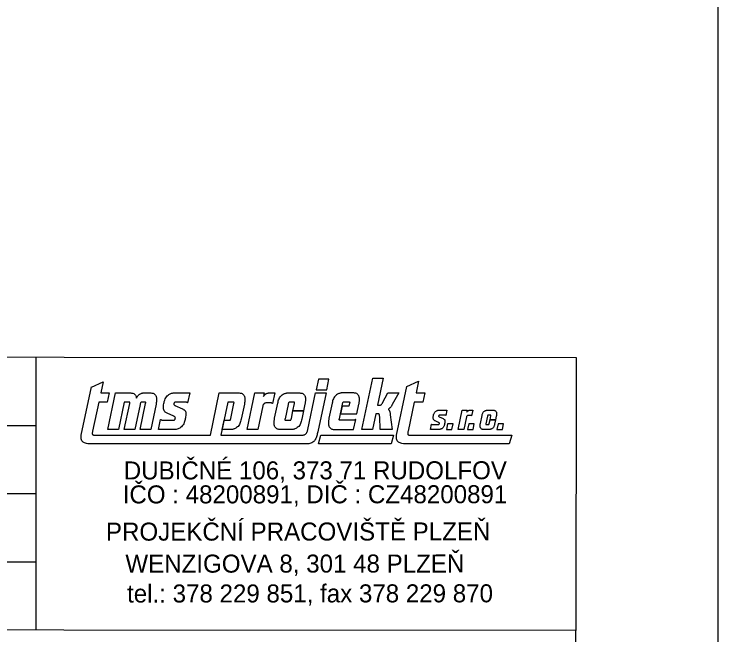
# Model space of a CAD drawing. Extents: x -467927 to -455912, y -1105662 to -1104439.
# Drawn here: x -458564.6 to -458490.4, y -1104682 to -1104616.5 of the extents above; entities that cross this region are included whole.
import ezdxf

# ---------------------------------------------------------------- set-up
doc = ezdxf.new("R2010")
doc.units = 0
doc.layers.add('Implicitní', color=7, linetype='Continuous')
doc.layers.add('Vše', color=7, linetype='Continuous')

msp = doc.modelspace()

# ---------------------------------------------------------------- linework, layer by layer
at = {"layer": 'Implicitní'}
for p, q in [((-458562.268, -1104652.701), (-458562.289, -1104681.501)), ((-458556.421, -1104655.845), (-458555.189, -1104655.283)), ((-458555.189, -1104655.283), (-458555.438, -1104656.467)), ((-458532.478, -1104655.021), (-458532.714, -1104656.139)), ((-458531.365, -1104655.021), (-458532.478, -1104655.021)), ((-458531.601, -1104656.139), (-458531.365, -1104655.021)), ((-458527.893, -1104660.331), (-458526.751, -1104654.911)), ((-458526.751, -1104654.911), (-458525.638, -1104654.911)), ((-458525.638, -1104654.911), (-458526.236, -1104657.75)), ((-458523.15, -1104655.796), (-458521.919, -1104655.235)), ((-458521.919, -1104655.235), (-458522.179, -1104656.467)), ((-458557.49, -1104660.925), (-458556.421, -1104655.844)), ((-458524.23, -1104660.925), (-458523.15, -1104655.796)), ((-458555.438, -1104656.467), (-458554.536, -1104656.467)), ((-458554.536, -1104656.467), (-458554.74, -1104657.433)), ((-458554.689, -1104660.331), (-458553.875, -1104656.467)), ((-458553.875, -1104656.467), (-458552.445, -1104656.467)), ((-458550.942, -1104656.467), (-458550.328, -1104656.467)), ((-458547.67, -1104656.467), (-458546.051, -1104656.467)), ((-458546.051, -1104656.467), (-458546.273, -1104657.52)), ((-458543.866, -1104660.92), (-458542.929, -1104656.467)), ((-458542.929, -1104656.467), (-458541.015, -1104656.467)), ((-458539.982, -1104660.331), (-458539.168, -1104656.467)), ((-458539.168, -1104656.467), (-458538.197, -1104656.467)), ((-458538.197, -1104656.467), (-458538.273, -1104656.83)), ((-458537.68, -1104656.467), (-458537.079, -1104656.467)), ((-458537.079, -1104656.467), (-458537.315, -1104657.588)), ((-458535.634, -1104656.467), (-458534.623, -1104656.467)), ((-458533.595, -1104660.322), (-458532.783, -1104656.467)), ((-458532.783, -1104656.467), (-458531.67, -1104656.467)), ((-458532.714, -1104656.139), (-458531.601, -1104656.139)), ((-458531.67, -1104656.467), (-458532.538, -1104660.591)), ((-458528.93, -1104656.467), (-458529.904, -1104656.467)), ((-458525.718, -1104657.51), (-458525.175, -1104656.467)), ((-458525.175, -1104656.467), (-458523.995, -1104656.467)), ((-458523.995, -1104656.467), (-458524.697, -1104657.697)), ((-458522.179, -1104656.467), (-458521.276, -1104656.467)), ((-458521.276, -1104656.467), (-458521.48, -1104657.433)), ((-458555.642, -1104657.433), (-458556.291, -1104660.517)), ((-458554.74, -1104657.433), (-458555.642, -1104657.433)), ((-458552.965, -1104657.433), (-458553.576, -1104660.331)), ((-458552.47, -1104657.433), (-458552.965, -1104657.433)), ((-458552.959, -1104660.331), (-458552.379, -1104657.576)), ((-458551.28, -1104660.331), (-458550.701, -1104657.577)), ((-458550.792, -1104657.433), (-458551.089, -1104657.433)), ((-458546.56, -1104657.433), (-458547.511, -1104657.433)), ((-458542.019, -1104657.433), (-458542.753, -1104660.92)), ((-458541.48, -1104657.433), (-458542.019, -1104657.433)), ((-458541.724, -1104659.163), (-458541.389, -1104657.575)), ((-458537.602, -1104657.5), (-458537.896, -1104657.5)), ((-458537.1, -1104659.144), (-458536.764, -1104657.548)), ((-458535.087, -1104657.433), (-458535.481, -1104657.433)), ((-458535.164, -1104658.369), (-458534.997, -1104657.575)), ((-458531.033, -1104657.55), (-458531.369, -1104659.142)), ((-458529.74, -1104657.396), (-458529.284, -1104657.396)), ((-458529.193, -1104657.539), (-458529.262, -1104657.865)), ((-458522.382, -1104657.433), (-458523.031, -1104660.517)), ((-458521.48, -1104657.433), (-458522.382, -1104657.433)), ((-458551.289, -1104657.687), (-458551.846, -1104660.331)), ((-458549.602, -1104657.647), (-458550.167, -1104660.331)), ((-458547.613, -1104657.789), (-458546.824, -1104658.141)), ((-458540.292, -1104657.649), (-458540.628, -1104659.246)), ((-458538.34, -1104657.822), (-458538.868, -1104660.331)), ((-458535.68, -1104657.687), (-458536.001, -1104659.214)), ((-458533.895, -1104657.652), (-458534.046, -1104658.369)), ((-458530.27, -1104659.214), (-458529.942, -1104657.654)), ((-458529.986, -1104657.865), (-458530.16, -1104658.688)), ((-458529.262, -1104657.865), (-458529.986, -1104657.865)), ((-458528.422, -1104658.688), (-458528.204, -1104657.653)), ((-458526.236, -1104657.75), (-458525.994, -1104657.75)), ((-458519.773, -1104658.295), (-458518.923, -1104658.295)), ((-458518.923, -1104658.295), (-458519.04, -1104658.848)), ((-458517.732, -1104660.323), (-458517.305, -1104658.295)), ((-458517.305, -1104658.295), (-458516.795, -1104658.295)), ((-458516.795, -1104658.295), (-458516.835, -1104658.485)), ((-458516.524, -1104658.295), (-458516.208, -1104658.295)), ((-458516.208, -1104658.295), (-458516.332, -1104658.883)), ((-458514.633, -1104658.295), (-458514.102, -1104658.295)), ((-458547.73, -1104658.933), (-458548.422, -1104658.623)), ((-458535.331, -1104659.163), (-458535.164, -1104658.369)), ((-458535.164, -1104658.369), (-458534.046, -1104658.369)), ((-458534.046, -1104658.369), (-458535.164, -1104658.369)), ((-458534.046, -1104658.369), (-458534.231, -1104659.248)), ((-458530.16, -1104658.688), (-458528.422, -1104658.688)), ((-458526.432, -1104658.68), (-458526.78, -1104660.331)), ((-458526.237, -1104658.68), (-458526.432, -1104658.68)), ((-458525.973, -1104660.331), (-458526.021, -1104659.005)), ((-458524.897, -1104658.782), (-458524.713, -1104660.331)), ((-458519.743, -1104658.988), (-458519.329, -1104659.173)), ((-458519.191, -1104658.802), (-458519.69, -1104658.802)), ((-458516.87, -1104659.006), (-458517.147, -1104660.323)), ((-458516.483, -1104658.837), (-458516.637, -1104658.837)), ((-458515.403, -1104659.7), (-458515.226, -1104658.862)), ((-458514.657, -1104658.935), (-458514.826, -1104659.737)), ((-458514.346, -1104658.802), (-458514.553, -1104658.802)), ((-458514.386, -1104659.293), (-458514.299, -1104658.876)), ((-458513.72, -1104658.917), (-458513.8, -1104659.293)), ((-458667.313, -1104659.823), (-458562.274, -1104659.9)), ((-458549.354, -1104660.331), (-458549.13, -1104659.269)), ((-458548.841, -1104659.357), (-458547.781, -1104659.357)), ((-458542.629, -1104660.331), (-458542.424, -1104659.357)), ((-458542.424, -1104659.357), (-458541.895, -1104659.357)), ((-458535.91, -1104659.357), (-458535.503, -1104659.357)), ((-458528.881, -1104659.357), (-458530.179, -1104659.357)), ((-458528.768, -1104660.331), (-458528.544, -1104659.267)), ((-458520.657, -1104660.323), (-458520.54, -1104659.766)), ((-458520.388, -1104659.812), (-458519.831, -1104659.812)), ((-458519.805, -1104659.589), (-458520.168, -1104659.427)), ((-458518.861, -1104659.736), (-458518.985, -1104660.323)), ((-458518.277, -1104659.736), (-458518.861, -1104659.736)), ((-458518.4, -1104660.323), (-458518.277, -1104659.736)), ((-458516.625, -1104659.736), (-458516.749, -1104660.323)), ((-458516.041, -1104659.736), (-458516.625, -1104659.736)), ((-458516.165, -1104660.323), (-458516.041, -1104659.736)), ((-458514.778, -1104659.812), (-458514.564, -1104659.812)), ((-458514.474, -1104659.71), (-458514.386, -1104659.293)), ((-458514.386, -1104659.293), (-458513.8, -1104659.293)), ((-458513.8, -1104659.293), (-458514.386, -1104659.293)), ((-458513.8, -1104659.293), (-458513.897, -1104659.755)), ((-458513.536, -1104659.736), (-458513.66, -1104660.323)), ((-458512.952, -1104659.736), (-458513.536, -1104659.736)), ((-458513.075, -1104660.323), (-458512.952, -1104659.736)), ((-458553.576, -1104660.331), (-458554.689, -1104660.331)), ((-458551.846, -1104660.331), (-458552.959, -1104660.331)), ((-458550.167, -1104660.331), (-458551.28, -1104660.331)), ((-458547.718, -1104660.331), (-458549.354, -1104660.331)), ((-458541.759, -1104660.331), (-458542.629, -1104660.331)), ((-458538.868, -1104660.331), (-458539.982, -1104660.331)), ((-458535.362, -1104660.331), (-458536.375, -1104660.331)), ((-458530.645, -1104660.331), (-458528.768, -1104660.331)), ((-458526.78, -1104660.331), (-458527.893, -1104660.331)), ((-458524.713, -1104660.331), (-458525.973, -1104660.331)), ((-458519.798, -1104660.323), (-458520.657, -1104660.323)), ((-458518.985, -1104660.323), (-458518.4, -1104660.323)), ((-458517.147, -1104660.323), (-458517.732, -1104660.323)), ((-458516.749, -1104660.323), (-458516.165, -1104660.323)), ((-458514.49, -1104660.323), (-458515.022, -1104660.323)), ((-458513.66, -1104660.323), (-458513.075, -1104660.323)), ((-458556.106, -1104660.92), (-458543.866, -1104660.92)), ((-458542.753, -1104660.92), (-458534.206, -1104660.92)), ((-458532.485, -1104661.848), (-458532.229, -1104660.92)), ((-458532.229, -1104660.92), (-458524.567, -1104660.92)), ((-458524.567, -1104660.92), (-458524.823, -1104661.848)), ((-458522.846, -1104660.92), (-458512.092, -1104660.92)), ((-458512.092, -1104660.92), (-458512.349, -1104661.848)), ((-458533.653, -1104661.848), (-458556.616, -1104661.848)), ((-458524.823, -1104661.848), (-458532.485, -1104661.848)), ((-458512.349, -1104661.848), (-458523.356, -1104661.848)), ((-458667.318, -1104667.023), (-458562.279, -1104667.1)), ((-458667.323, -1104674.223), (-458562.284, -1104674.3))]:
    msp.add_line(p, q, dxfattribs=at)
for points in [[(-458667.307, -1104652.623), (-458505.302, -1104652.742), (-458505.323, -1104681.543), (-458667.328, -1104681.424)], [(-458667.332, -1104688.623), (-458505.329, -1104688.742), (-458505.323, -1104681.543), (-458667.326, -1104681.424)]]:
    msp.add_lwpolyline(points, close=True, dxfattribs=at)
for points in [[(-458552.445, -1104656.467), (-458552.353, -1104656.468), (-458552.176, -1104656.481), (-458552.033, -1104656.512), (-458551.889, -1104656.596), (-458551.715, -1104656.826), (-458551.685, -1104656.938), (-458551.673, -1104656.986), (-458551.666, -1104657.015)], [(-458551.666, -1104657.015), (-458551.562, -1104656.84), (-458551.454, -1104656.712), (-458551.319, -1104656.601), (-458551.227, -1104656.549), (-458551.121, -1104656.505), (-458551.037, -1104656.484), (-458550.942, -1104656.467)], [(-458550.328, -1104656.467), (-458550.236, -1104656.468), (-458550.06, -1104656.481), (-458549.916, -1104656.512), (-458549.773, -1104656.596), (-458549.599, -1104656.826), (-458549.569, -1104656.938), (-458549.556, -1104656.986), (-458549.561, -1104657.341), (-458549.579, -1104657.501), (-458549.602, -1104657.647)], [(-458548.422, -1104658.623), (-458548.566, -1104658.53), (-458548.677, -1104658.435), (-458548.778, -1104658.261), (-458548.816, -1104658.057), (-458548.82, -1104657.859), (-458548.784, -1104657.574), (-458548.733, -1104657.362), (-458548.634, -1104657.103), (-458548.505, -1104656.881), (-458548.341, -1104656.715), (-458548.123, -1104656.564), (-458547.955, -1104656.499), (-458547.792, -1104656.469), (-458547.67, -1104656.467)], [(-458541.015, -1104656.467), (-458540.923, -1104656.468), (-458540.747, -1104656.481), (-458540.603, -1104656.512), (-458540.46, -1104656.596), (-458540.285, -1104656.826), (-458540.255, -1104656.938), (-458540.243, -1104656.986), (-458540.247, -1104657.341), (-458540.265, -1104657.501), (-458540.292, -1104657.649)], [(-458538.273, -1104656.83), (-458538.203, -1104656.732), (-458538.147, -1104656.669), (-458538.061, -1104656.594), (-458537.985, -1104656.548), (-458537.88, -1104656.501), (-458537.79, -1104656.478), (-458537.68, -1104656.467)], [(-458536.764, -1104657.548), (-458536.713, -1104657.322), (-458536.632, -1104657.092), (-458536.505, -1104656.874), (-458536.379, -1104656.732), (-458536.199, -1104656.613), (-458536.046, -1104656.539), (-458535.916, -1104656.496), (-458535.795, -1104656.471), (-458535.634, -1104656.467)], [(-458534.623, -1104656.467), (-458534.531, -1104656.468), (-458534.355, -1104656.481), (-458534.211, -1104656.512), (-458534.068, -1104656.596), (-458533.893, -1104656.826), (-458533.863, -1104656.938), (-458533.851, -1104656.986), (-458533.855, -1104657.341), (-458533.873, -1104657.501), (-458533.895, -1104657.652)], [(-458529.904, -1104656.467), (-458530.064, -1104656.471), (-458530.185, -1104656.496), (-458530.316, -1104656.539), (-458530.468, -1104656.613), (-458530.648, -1104656.732), (-458530.775, -1104656.874), (-458530.902, -1104657.092), (-458530.983, -1104657.322), (-458531.033, -1104657.55)], [(-458528.204, -1104657.653), (-458528.181, -1104657.501), (-458528.163, -1104657.341), (-458528.158, -1104656.986), (-458528.171, -1104656.938), (-458528.201, -1104656.826), (-458528.375, -1104656.596), (-458528.519, -1104656.512), (-458528.662, -1104656.481), (-458528.838, -1104656.468), (-458528.93, -1104656.467)], [(-458552.379, -1104657.576), (-458552.373, -1104657.542), (-458552.368, -1104657.503), (-458552.374, -1104657.469), (-458552.392, -1104657.445), (-458552.426, -1104657.435), (-458552.47, -1104657.433)], [(-458551.089, -1104657.433), (-458551.117, -1104657.434), (-458551.15, -1104657.442), (-458551.184, -1104657.463), (-458551.228, -1104657.51), (-458551.25, -1104657.556), (-458551.289, -1104657.687)], [(-458550.701, -1104657.577), (-458550.695, -1104657.542), (-458550.69, -1104657.503), (-458550.696, -1104657.469), (-458550.714, -1104657.445), (-458550.747, -1104657.435), (-458550.792, -1104657.433)], [(-458547.511, -1104657.433), (-458547.587, -1104657.44), (-458547.629, -1104657.461), (-458547.673, -1104657.497), (-458547.704, -1104657.55), (-458547.723, -1104657.613), (-458547.725, -1104657.681), (-458547.705, -1104657.726), (-458547.661, -1104657.759), (-458547.613, -1104657.789)], [(-458546.273, -1104657.52), (-458546.336, -1104657.485), (-458546.401, -1104657.457), (-458546.441, -1104657.445), (-458546.51, -1104657.435), (-458546.56, -1104657.433)], [(-458541.389, -1104657.575), (-458541.383, -1104657.542), (-458541.378, -1104657.503), (-458541.384, -1104657.469), (-458541.402, -1104657.445), (-458541.435, -1104657.435), (-458541.48, -1104657.433)], [(-458537.896, -1104657.5), (-458537.967, -1104657.506), (-458538.037, -1104657.519), (-458538.12, -1104657.553), (-458538.191, -1104657.593), (-458538.246, -1104657.642), (-458538.308, -1104657.727), (-458538.34, -1104657.822)], [(-458537.315, -1104657.588), (-458537.379, -1104657.552), (-458537.444, -1104657.524), (-458537.483, -1104657.512), (-458537.535, -1104657.504), (-458537.602, -1104657.5)], [(-458535.481, -1104657.433), (-458535.509, -1104657.434), (-458535.542, -1104657.442), (-458535.576, -1104657.463), (-458535.62, -1104657.51), (-458535.642, -1104657.556), (-458535.681, -1104657.687)], [(-458534.997, -1104657.575), (-458534.99, -1104657.542), (-458534.985, -1104657.503), (-458534.991, -1104657.469), (-458535.01, -1104657.445), (-458535.043, -1104657.435), (-458535.087, -1104657.433)], [(-458529.942, -1104657.654), (-458529.902, -1104657.52), (-458529.879, -1104657.473), (-458529.836, -1104657.427), (-458529.802, -1104657.406), (-458529.769, -1104657.398), (-458529.74, -1104657.396)], [(-458529.284, -1104657.396), (-458529.239, -1104657.398), (-458529.206, -1104657.408), (-458529.188, -1104657.432), (-458529.181, -1104657.467), (-458529.186, -1104657.505), (-458529.193, -1104657.539)], [(-458525.994, -1104657.75), (-458525.925, -1104657.747), (-458525.898, -1104657.738), (-458525.858, -1104657.713), (-458525.826, -1104657.677), (-458525.734, -1104657.54), (-458525.718, -1104657.51)], [(-458546.824, -1104658.141), (-458546.771, -1104658.167), (-458546.666, -1104658.237), (-458546.587, -1104658.306), (-458546.511, -1104658.405), (-458546.477, -1104658.492), (-458546.454, -1104658.728), (-458546.486, -1104658.993), (-458546.571, -1104659.387), (-458546.636, -1104659.595), (-458546.753, -1104659.836), (-458546.931, -1104660.048), (-458547.102, -1104660.179), (-458547.286, -1104660.27), (-458547.49, -1104660.319), (-458547.718, -1104660.331)], [(-458524.697, -1104657.697), (-458524.788, -1104657.856), (-458524.859, -1104657.956), (-458524.934, -1104658.035), (-458524.999, -1104658.094), (-458525.103, -1104658.172)], [(-458525.103, -1104658.172), (-458525.053, -1104658.254), (-458525.006, -1104658.329), (-458524.973, -1104658.395), (-458524.941, -1104658.498), (-458524.914, -1104658.638), (-458524.897, -1104658.782)], [(-458520.168, -1104659.427), (-458520.244, -1104659.378), (-458520.302, -1104659.328), (-458520.355, -1104659.236), (-458520.375, -1104659.129), (-458520.377, -1104659.025), (-458520.358, -1104658.876), (-458520.331, -1104658.764), (-458520.279, -1104658.628), (-458520.212, -1104658.512), (-458520.125, -1104658.425), (-458520.011, -1104658.346), (-458519.923, -1104658.311), (-458519.837, -1104658.296), (-458519.773, -1104658.295)], [(-458516.835, -1104658.485), (-458516.798, -1104658.434), (-458516.768, -1104658.401), (-458516.723, -1104658.361), (-458516.684, -1104658.337), (-458516.628, -1104658.313), (-458516.581, -1104658.301), (-458516.524, -1104658.295)], [(-458515.226, -1104658.862), (-458515.2, -1104658.743), (-458515.157, -1104658.623), (-458515.091, -1104658.508), (-458515.024, -1104658.434), (-458514.93, -1104658.371), (-458514.849, -1104658.332), (-458514.781, -1104658.31), (-458514.718, -1104658.297), (-458514.633, -1104658.295)], [(-458514.102, -1104658.294), (-458514.054, -1104658.295), (-458513.961, -1104658.302), (-458513.886, -1104658.318), (-458513.811, -1104658.362), (-458513.719, -1104658.483), (-458513.704, -1104658.542), (-458513.697, -1104658.567), (-458513.699, -1104658.754), (-458513.709, -1104658.837), (-458513.72, -1104658.917)], [(-458547.781, -1104659.357), (-458547.707, -1104659.353), (-458547.663, -1104659.327), (-458547.609, -1104659.268), (-458547.579, -1104659.195), (-458547.567, -1104659.102), (-458547.579, -1104659.044), (-458547.608, -1104659.006), (-458547.673, -1104658.966), (-458547.73, -1104658.933)], [(-458526.021, -1104659.005), (-458526.033, -1104658.856), (-458526.046, -1104658.754), (-458526.078, -1104658.717), (-458526.122, -1104658.693), (-458526.16, -1104658.683), (-458526.237, -1104658.68)], [(-458519.69, -1104658.802), (-458519.73, -1104658.805), (-458519.751, -1104658.816), (-458519.775, -1104658.835), (-458519.791, -1104658.863), (-458519.801, -1104658.896), (-458519.802, -1104658.932), (-458519.791, -1104658.956), (-458519.769, -1104658.973), (-458519.743, -1104658.988)], [(-458519.04, -1104658.848), (-458519.073, -1104658.829), (-458519.107, -1104658.814), (-458519.128, -1104658.808), (-458519.164, -1104658.803), (-458519.191, -1104658.802)], [(-458516.637, -1104658.837), (-458516.674, -1104658.84), (-458516.711, -1104658.847), (-458516.754, -1104658.865), (-458516.792, -1104658.885), (-458516.821, -1104658.911), (-458516.853, -1104658.956), (-458516.87, -1104659.006)], [(-458516.332, -1104658.883), (-458516.365, -1104658.864), (-458516.4, -1104658.849), (-458516.42, -1104658.843), (-458516.447, -1104658.839), (-458516.483, -1104658.837)], [(-458514.553, -1104658.802), (-458514.567, -1104658.803), (-458514.585, -1104658.807), (-458514.603, -1104658.818), (-458514.626, -1104658.842), (-458514.638, -1104658.866), (-458514.658, -1104658.935)], [(-458514.299, -1104658.876), (-458514.295, -1104658.859), (-458514.292, -1104658.839), (-458514.296, -1104658.82), (-458514.305, -1104658.808), (-458514.323, -1104658.803), (-458514.346, -1104658.802)], [(-458549.13, -1104659.269), (-458549.067, -1104659.305), (-458549.002, -1104659.333), (-458548.963, -1104659.345), (-458548.893, -1104659.355), (-458548.841, -1104659.357)], [(-458541.895, -1104659.357), (-458541.828, -1104659.354), (-458541.783, -1104659.328), (-458541.756, -1104659.274), (-458541.741, -1104659.226), (-458541.724, -1104659.163)], [(-458540.628, -1104659.246), (-458540.68, -1104659.476), (-458540.761, -1104659.706), (-458540.888, -1104659.923), (-458541.015, -1104660.066), (-458541.195, -1104660.185), (-458541.347, -1104660.259), (-458541.478, -1104660.302), (-458541.599, -1104660.326), (-458541.759, -1104660.331)], [(-458536.375, -1104660.331), (-458536.467, -1104660.33), (-458536.643, -1104660.317), (-458536.787, -1104660.285), (-458536.93, -1104660.202), (-458537.105, -1104659.971), (-458537.135, -1104659.86), (-458537.147, -1104659.811), (-458537.143, -1104659.456), (-458537.125, -1104659.297), (-458537.1, -1104659.144)], [(-458536.001, -1104659.214), (-458536.008, -1104659.248), (-458536.013, -1104659.287), (-458536.006, -1104659.321), (-458535.988, -1104659.345), (-458535.955, -1104659.355), (-458535.91, -1104659.357)], [(-458535.503, -1104659.357), (-458535.435, -1104659.354), (-458535.39, -1104659.328), (-458535.363, -1104659.274), (-458535.349, -1104659.226), (-458535.331, -1104659.163)], [(-458534.231, -1104659.248), (-458534.283, -1104659.476), (-458534.364, -1104659.706), (-458534.491, -1104659.923), (-458534.617, -1104660.066), (-458534.797, -1104660.185), (-458534.95, -1104660.259), (-458535.08, -1104660.302), (-458535.201, -1104660.326), (-458535.362, -1104660.331)], [(-458531.369, -1104659.142), (-458531.395, -1104659.297), (-458531.412, -1104659.456), (-458531.417, -1104659.811), (-458531.404, -1104659.86), (-458531.374, -1104659.971), (-458531.2, -1104660.202), (-458531.057, -1104660.285), (-458530.913, -1104660.317), (-458530.737, -1104660.33), (-458530.645, -1104660.331)], [(-458530.179, -1104659.357), (-458530.224, -1104659.355), (-458530.257, -1104659.345), (-458530.275, -1104659.321), (-458530.282, -1104659.287), (-458530.277, -1104659.248), (-458530.27, -1104659.214)], [(-458528.545, -1104659.267), (-458528.598, -1104659.299), (-458528.669, -1104659.333), (-458528.77, -1104659.356), (-458528.881, -1104659.357)], [(-458520.54, -1104659.766), (-458520.507, -1104659.785), (-458520.472, -1104659.799), (-458520.452, -1104659.805), (-458520.415, -1104659.811), (-458520.388, -1104659.812)], [(-458519.831, -1104659.812), (-458519.792, -1104659.81), (-458519.77, -1104659.796), (-458519.741, -1104659.765), (-458519.725, -1104659.727), (-458519.719, -1104659.678), (-458519.725, -1104659.648), (-458519.741, -1104659.627), (-458519.775, -1104659.607), (-458519.805, -1104659.589)], [(-458519.329, -1104659.173), (-458519.301, -1104659.187), (-458519.246, -1104659.224), (-458519.205, -1104659.26), (-458519.165, -1104659.312), (-458519.147, -1104659.358), (-458519.135, -1104659.481), (-458519.152, -1104659.621), (-458519.196, -1104659.827), (-458519.231, -1104659.937), (-458519.292, -1104660.063), (-458519.385, -1104660.175), (-458519.475, -1104660.243), (-458519.572, -1104660.291), (-458519.679, -1104660.317), (-458519.798, -1104660.323)], [(-458515.022, -1104660.323), (-458515.071, -1104660.322), (-458515.163, -1104660.316), (-458515.238, -1104660.299), (-458515.314, -1104660.255), (-458515.405, -1104660.134), (-458515.421, -1104660.076), (-458515.428, -1104660.05), (-458515.425, -1104659.864), (-458515.416, -1104659.78), (-458515.403, -1104659.7)], [(-458514.826, -1104659.737), (-458514.829, -1104659.755), (-458514.832, -1104659.775), (-458514.829, -1104659.793), (-458514.819, -1104659.805), (-458514.802, -1104659.811), (-458514.778, -1104659.812)], [(-458514.564, -1104659.812), (-458514.529, -1104659.81), (-458514.505, -1104659.797), (-458514.491, -1104659.768), (-458514.483, -1104659.743), (-458514.474, -1104659.71)], [(-458513.897, -1104659.755), (-458513.924, -1104659.874), (-458513.966, -1104659.995), (-458514.033, -1104660.109), (-458514.099, -1104660.184), (-458514.194, -1104660.246), (-458514.274, -1104660.285), (-458514.343, -1104660.308), (-458514.406, -1104660.321), (-458514.49, -1104660.323)], [(-458556.291, -1104660.517), (-458556.314, -1104660.625), (-458556.328, -1104660.734), (-458556.318, -1104660.831), (-458556.266, -1104660.892), (-458556.195, -1104660.912), (-458556.106, -1104660.92)], [(-458534.206, -1104660.92), (-458534.085, -1104660.916), (-458533.949, -1104660.878), (-458533.847, -1104660.817), (-458533.751, -1104660.731), (-458533.656, -1104660.549), (-458533.626, -1104660.443), (-458533.595, -1104660.322)], [(-458523.031, -1104660.517), (-458523.054, -1104660.625), (-458523.068, -1104660.734), (-458523.058, -1104660.831), (-458523.007, -1104660.892), (-458522.935, -1104660.912), (-458522.846, -1104660.92)], [(-458556.616, -1104661.848), (-458556.95, -1104661.807), (-458557.134, -1104661.752), (-458557.29, -1104661.671), (-458557.425, -1104661.53), (-458557.504, -1104661.303), (-458557.514, -1104661.139), (-458557.49, -1104660.925)], [(-458532.538, -1104660.591), (-458532.656, -1104660.998), (-458532.727, -1104661.202), (-458532.806, -1104661.37), (-458532.891, -1104661.516), (-458533.052, -1104661.679), (-458533.271, -1104661.786), (-458533.487, -1104661.843), (-458533.653, -1104661.848)], [(-458523.356, -1104661.848), (-458523.69, -1104661.807), (-458523.874, -1104661.752), (-458524.03, -1104661.671), (-458524.165, -1104661.53), (-458524.244, -1104661.303), (-458524.254, -1104661.139), (-458524.23, -1104660.925)]]:
    msp.add_spline(points, degree=3, dxfattribs=at)
at = {"layer": 'Vše'}
msp.add_lwpolyline([(-458910.353, -1104438.908), (-458490.353, -1104438.908), (-458490.352, -1104735.908), (-458910.352, -1104735.908)], close=True, dxfattribs=at)

# ---------------------------------------------------------------- texts
at = {"layer": 'Implicitní'}
for s, p in [('DUBIČNÉ 106, 373 71 RUDOLFOV', (-458553.003, -1104665.603)), ('IČO : 48200891, DIČ : CZ48200891', (-458553.114, -1104668.132)), ('PROJEKČNÍ PRACOVIŠTĚ PLZEŇ', (-458554.886, -1104672.061)), ('WENZIGOVA 8, 301 48 PLZEŇ', (-458552.834, -1104675.442)), ('tel.: 378 229 851, fax 378 229 870', (-458552.655, -1104678.591))]:
    msp.add_text(s, height=1.9008, rotation=0.03338, dxfattribs=at).set_placement(p)

doc.saveas('drawing.dxf')
